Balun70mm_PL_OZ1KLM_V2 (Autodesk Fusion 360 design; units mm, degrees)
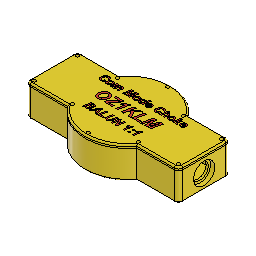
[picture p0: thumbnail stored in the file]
part number: 2026-06-13-11-17-23-040
part number: 2026-06-13-15-12-59-536
part number: 2026-06-16-10-17-01-501
part number: 2026-06-16-10-40-35-221
part number: 2026-06-16-15-31-44-028
part number: 2026-06-16-15-38-57-578
part number: 2026-06-16-16-55-37-971
part number: 2026-06-18-19-06-49-878
part number: 2026-06-18-21-17-26-018
part number: 2026-06-18-21-43-53-385
sketch "Grundtegning" plane through (0, 0, 0) normal (0, 0, 1) x axis (1, 0, 0)
  line L1 (-66.7111, -18.5) -> (-29.7111, -18.5)
  line L2 (-66.7111, 18.5) -> (-66.7111, -18.5)
  line L3 (-29.7111, 18.5) -> (-66.7111, 18.5)
  line L4 (66.7111, 18.5) -> (29.7111, 18.5)
  line L5 (66.7111, -18.5) -> (66.7111, 18.5)
  line L6 (29.7111, -18.5) -> (66.7111, -18.5)
  line L7 (-68.7111, -24.5) -> (-32.8748, -24.5)
  line L8 (-72.7111, 20.5) -> (-72.7111, -20.5)
  line L9 (-32.8748, 24.5) -> (-68.7111, 24.5)
  line L10 (68.7111, 24.5) -> (32.8748, 24.5)
  line L11 (72.7111, -20.5) -> (72.7111, 20.5)
  line L12 (32.8748, -24.5) -> (68.7111, -24.5)
  arc A1 centre (0, 0) radius 41 clockwise from (32.8748, -24.5) to (-32.8748, -24.5)
  arc A2 centre (0, 0) radius 41 clockwise from (-32.8748, 24.5) to (32.8748, 24.5)
  arc A3 centre (0, 0) radius 35 clockwise from (29.7111, -18.5) to (-29.7111, -18.5)
  arc A4 centre (0, 0) radius 35 clockwise from (-29.7111, 18.5) to (29.7111, 18.5)
  arc A5 centre (68.7111, 20.5) radius 4 clockwise from (68.7111, 24.5) to (72.7111, 20.5)
  arc A6 centre (68.7111, -20.5) radius 4 clockwise from (72.7111, -20.5) to (68.7111, -24.5)
  arc A7 centre (-68.7111, -20.5) radius 4 clockwise from (-68.7111, -24.5) to (-72.7111, -20.5)
  arc A8 centre (-68.7111, 20.5) radius 4 clockwise from (-72.7111, 20.5) to (-68.7111, 24.5)
  point P1 (0, 0)
  point P2 (0, 0)
  point P17 (72.7111, 24.5)
  point P13 (-72.7111, -24.5)
  point P14 (-72.7111, 24.5)
  point P7 (-29.7111, 18.5)
  point P8 (29.7111, 18.5)
  point P12 (-32.8748, -24.5)
  point P15 (-32.8748, 24.5)
  point P16 (32.8748, 24.5)
  coincident P1 P2
  concentric A1 A3
  horizontal L1
  vertical L2
  horizontal L3
  horizontal L4
  vertical L5
  horizontal L6
  horizontal L7
  vertical L8
  horizontal L9
  horizontal L10
  vertical L11
  horizontal L12
  concentric A3 A4
  coincident P17 L10
  coincident P17 L11
  tangent L10 A5
  tangent L11 A5
  tangent L11 A6
  tangent L12 A6
  equal A5 A6
  coincident P13 L7
  coincident P13 L8
  tangent L7 A7
  tangent L8 A7
  equal A5 A7
  coincident P14 L8
  coincident P14 L9
  tangent L8 A8
  tangent L9 A8
  equal A5 A8
  dimension "d1" diameter A3 = 70
  dimension "d2" diameter A1 = 82 (= "d1 + ( ( ( 2 + 2 + 2 ) * 2 ) * 1 mm )")
  dimension "d6" distance L1 L3 = 37 (= "( d1 / 2 ) + 2 mm")
  dimension "d10" distance L4 L6 = 37 (= "( d1 / 2 ) + 2 mm")
  dimension "d12" distance L7 L9 = 49 (= "d6 + 12 mm")
  dimension "d13" distance L2 L8 = 6
  dimension "d14" distance L5 L11 = 6 (= "d13")
  dimension "d15" distance L10 L12 = 49 (= "d12")
  dimension "d27" distance P1 L7 = 24.5 (= "d12 / 2")
  dimension "d28" distance P1 L1 = 18.5
  dimension "d29" distance P2 L6 = 18.5 (= "d10 / 2")
  dimension "d30" distance P1 L12 = 24.5 (= "d15 / 2")
  dimension "d31" distance P7 L2 = 37 (= "d6")
  dimension "d32" distance P7 P8 = 59.4222
  dimension "d33" distance P8 L5 = 37 (= "d10")
  dimension "d36" radius A2 = 41 (= "d2 / 2")
  dimension "d37" distance P12 P13 = 39.8363
  dimension "d38" distance P14 P15 = 39.8363 (= "d37")
  dimension "d39" distance P16 P17 = 39.8363 (= "d37")
  dimension "d40" radius A5 = 4
  dimension "d158" distance L8 L11 = 145.4222
sketch "SkrueHulTegning" plane through (0, 0, 0) normal (0, 0, 1) x axis (1, 0, 0)
  line L1 (69.711, 21.5) -> (-69.711, 21.5)
  line L2 (69.711, -21.5) -> (-69.711, -21.5)
  line L3 (-69.711, -21.5) -> (-69.711, 21.5)
  line L4 (69.711, -21.5) -> (69.711, 21.5)
  line L5 (69.711, 0) -> (-69.711, 0)
  line L6 (0, -38) -> (0, 38)
  circle C1 centre (0, 0) radius 38
  circle C2 centre (-68.911, 20.7) radius 1
  circle C3 centre (-68.911, -20.7) radius 1
  circle C4 centre (68.911, -20.7) radius 1
  circle C5 centre (68.911, 20.7) radius 1
  circle C6 centre (-31.3329, 21.5) radius 1
  circle C7 centre (31.3329, 21.5) radius 1
  circle C8 centre (0, 38) radius 1
  circle C9 centre (-31.3329, -21.5) radius 1
  circle C10 centre (0, -38) radius 1
  circle C11 centre (31.3329, -21.5) radius 1
  point P1 (0, 0)
  point P2 (0, 0)
  point P6 (69.711, 21.5)
  point P3 (69.711, -21.5)
  point P4 (-69.711, 21.5)
  point P5 (-69.711, -21.5)
  point P7 (-69.711, 0)
  point P8 (69.711, 0)
  point P9 (0, 38)
  point P10 (0, -38)
  point P15 (-31.3329, 21.5)
  point P16 (31.3329, 21.5)
  point P17 (0, 38)
  point P18 (-31.3329, -21.5)
  point P19 (0, -38)
  point P20 (31.3329, -21.5)
  point P11 (-68.911, 20.7)
  point P12 (-68.911, -20.7)
  point P13 (68.911, -20.7)
  point P14 (68.911, 20.7)
  coincident P1 P2
  horizontal L1
  horizontal L2
  perpendicular L2 L3
  perpendicular L2 L4
  coincident L1 P6
  coincident P3 L4
  coincident L1 P4
  coincident L2 P5
  midpoint L3 P7
  midpoint L4 P8
  coincident C1 P9
  coincident C1 P10
  perpendicular L5 L6
  coincident C1 P15
  coincident L1 P15
  coincident C1 P16
  coincident L1 P16
  coincident P9 P17
  coincident P2 L6
  coincident L2 P18
  coincident C1 P18
  coincident P10 P19
  coincident L2 P20
  coincident C1 P20
  dimension "d41" diameter C1 = 76 (= "70 mm + ( 6 mm )")
  dimension "d42" distance P2 L1 = 21.5
  dimension "d43" distance P2 L2 = 21.5
  dimension "d44" distance P2 L3 = 69.711
  dimension "d45" distance P1 L4 = 69.711
  dimension "d47" diameter C2 = 2
  dimension "d48" distance L1 P11 = 0.8 (= "d49")
  dimension "d49" distance L3 P11 = 0.8
  dimension "d50" diameter C3 = 2 (= "d47")
  dimension "d51" distance L3 P12 = 0.8 (= "d49")
  dimension "d52" distance L2 P12 = 0.8 (= "d49")
  dimension "d53" diameter C4 = 2 (= "d47")
  dimension "d54" diameter C5 = 2 (= "d47")
  dimension "d55" distance L4 P13 = 0.8 (= "d49")
  dimension "d56" distance L2 P13 = 0.8 (= "d49")
  dimension "d57" distance L4 P14 = 0.8 (= "d49")
  dimension "d58" distance L1 P14 = 0.8 (= "d49")
  dimension "d59" diameter C6 = 2 (= "d47")
  dimension "d60" diameter C7 = 2 (= "d47")
  dimension "d61" diameter C8 = 2 (= "d47")
  dimension "d62" diameter C9 = 2 (= "d47")
  dimension "d63" diameter C10 = 2 (= "d47")
  dimension "d64" diameter C11 = 2 (= "d47")
sketch "Case_Intern" plane through (0, 0, 0) normal (0, 0, 1) x axis (1, 0, 0)
  line L1 (12.6491, 3) -> (-12.6491, 3)
  line L2 (12.6491, -3) -> (-12.6491, -3)
  line L3 (9.1924, -9.1924) -> (0, 0)
  line L4 (13, 0) -> (0, 0)
  line L5 (9.1924, 9.1924) -> (0, 0)
  line L6 (-9.1924, 9.1924) -> (0, 0)
  line L7 (-9.1924, -9.1924) -> (0, 0)
  line L8 (8.3046, -10.0017) -> (-10.0017, 8.3046)
  line L9 (10.0017, -8.3046) -> (-8.3046, 10.0017)
  line L10 (8.3046, 10.0017) -> (-10.0017, -8.3046)
  line L11 (10.0017, 8.3046) -> (-8.3046, -10.0017)
  circle C1 centre (0, 0) radius 13
  circle C2 centre (0, 0) radius 15
  point P1 (0, 0)
  point P2 (0, 0)
  point P3 (0, 0)
  point P4 (-12.6491, 3)
  point P5 (12.6491, 3)
  point P6 (-12.6491, -3)
  point P7 (12.6491, -3)
  point P8 (0, 0)
  point P11 (0, 0)
  point P12 (9.1924, 9.1924)
  point P13 (0, 0)
  point P14 (-9.1924, 9.1924)
  point P15 (-9.1924, -9.1924)
  point P16 (-10.0017, 8.3046)
  point P17 (8.3046, -10.0017)
  point P18 (-8.3046, 10.0017)
  point P19 (10.0017, -8.3046)
  point P20 (-10.0017, -8.3046)
  point P21 (8.3046, 10.0017)
  point P22 (-8.3046, -10.0017)
  point P23 (10.0017, 8.3046)
  coincident P1 P2
  coincident P1 P3
  coincident C1 P4
  coincident C1 P5
  horizontal L1
  coincident C1 P6
  coincident C1 P7
  parallel L1 L2
  horizontal L4
  coincident P3 P8
  coincident P1 P11
  coincident C1 P12
  perpendicular L3 L5
  coincident P2 P13
  coincident C1 P14
  perpendicular L5 L6
  coincident C1 P15
  perpendicular L6 L7
  coincident C1 P16
  coincident C1 P17
  coincident C1 P18
  coincident C1 P19
  parallel L8 L9
  coincident C1 P20
  coincident C1 P21
  perpendicular L9 L10
  coincident C1 P22
  coincident C1 P23
  perpendicular L9 L11
  parallel L3 L8
  dimension "d159" diameter C1 = 26
  dimension "d160" diameter C2 = 30
  dimension "d161" distance L1 L2 = 6
  dimension "d162" distance P2 L2 = 3
  dimension "d163" angle L3 L4 = 45
  dimension "d164" distance L6 L8 = 1.2
  dimension "d165" distance L6 L9 = 1.2
  dimension "d166" distance L5 L10 = 1.2
  dimension "d167" distance L5 L11 = 1.2
sketch "Case_Intern_2" plane through (0, 0, 0) normal (0, 0, 1) x axis (1, 0, 0)
  line L1 (12.6491, 3) -> (-12.6491, 3)
  line L2 (12.6491, -3) -> (-12.6491, -3)
  line L3 (13, 0) -> (0, 0)
  line L4 (-4.6971, 3) -> (-10.0017, 8.3046)
  line L5 (-1.3029, 3) -> (-8.3046, 10.0017)
  line L6 (10.0017, -8.3046) -> (4.6971, -3)
  line L7 (8.3046, -10.0017) -> (1.3029, -3)
  line L8 (10.0017, 8.3046) -> (4.6971, 3)
  line L9 (8.3046, 10.0017) -> (1.3029, 3)
  line L10 (-4.6971, -3) -> (-10.0017, -8.3046)
  line L11 (-1.3029, -3) -> (-8.3046, -10.0017)
  circle C1 centre (0, 0) radius 13
  circle C2 centre (0, 0) radius 15
  point P6 (0, 0)
  point P9 (0, 0)
  point P2 (0, 0)
  point P8 (-12.6491, 3)
  point P5 (12.6491, 3)
  point P3 (-12.6491, -3)
  point P7 (12.6491, -3)
  point P10 (0, 0)
  point P4 (-10.0017, 8.3046)
  point P14 (8.3046, -10.0017)
  point P17 (-8.3046, 10.0017)
  point P18 (10.0017, -8.3046)
  point P15 (-10.0017, -8.3046)
  point P16 (8.3046, 10.0017)
  point P12 (-8.3046, -10.0017)
  point P13 (10.0017, 8.3046)
  point P1 (0, 0)
  point P19 (-4.6971, 3)
  point P20 (-1.3029, 3)
  point P21 (4.6971, -3)
  point P22 (1.3029, -3)
  point P23 (4.6971, 3)
  point P24 (1.3029, 3)
  point P25 (-4.6971, -3)
  point P26 (-1.3029, -3)
  coincident P6 P9
  coincident P2 P9
  coincident P8 C1
  coincident P5 C1
  horizontal L1
  coincident P3 C1
  coincident P7 C1
  parallel L1 L2
  horizontal L3
  coincident P2 P10
  coincident P4 C1
  coincident P14 C1
  coincident P17 C1
  coincident P18 C1
  parallel L4 L5
  coincident P15 C1
  coincident P16 C1
  coincident P12 C1
  coincident P13 C1
  coincident P1 P6
  coincident L1 P19
  coincident L1 P20
  coincident L2 P21
  coincident L2 P22
  coincident L1 P23
  coincident L1 P24
  coincident L2 P25
  coincident L2 P26
  dimension "d222" diameter C1 = 26
  dimension "d223" diameter C2 = 30
  dimension "d224" distance L1 L2 = 6
  dimension "d225" distance P6 L2 = 3
  dimension "d231" distance L8 L9 = 2.4
  dimension "d232" distance L6 L7 = 2.4
  dimension "d233" distance L10 L11 = 2.4
  dimension "d234" distance L4 L5 = 2.4
  dimension "d235" distance P1 L7 = 1.2
  dimension "d236" angle L3 L6 = 45
  dimension "d237" angle L7 L11 = 90
  dimension "d238" distance P1 L11 = 1.2
  dimension "d239" angle L3 L8 = 45
  dimension "d240" angle L5 L9 = 90
  dimension "d241" distance P1 L5 = 1.2
  dimension "d242" distance P1 L9 = 1.2
sketch "TopTegning" plane through (0, 0, 0) normal (0, 0, 1) x axis (1, 0, 0)
  line L1 (72.6153, 0) -> (-72.6153, 0)
  line L2 (0, -41.1317) -> (0, 40.7932)
  line L3 (-68.911, -39.9689) -> (-68.911, 40.0995)
  line L4 (68.911, -40.6095) -> (68.911, 39.886)
  line L5 (31.3329, 21.5) -> (-31.3329, 21.5)
  line L6 (31.3329, -21.5) -> (-31.3329, -21.5)
  line L7 (71.9932, 20.7) -> (-72.6153, 20.7)
  line L8 (72.2067, -20.7) -> (-72.557, -20.7)
  line L9 (66.7111, 16) -> (66.7111, 18.5)
  line L10 (-66.7111, 18.5) -> (-66.7111, 16)
  line L11 (66.7111, -16) -> (66.7111, -18.5)
  line L12 (-66.7111, -18.5) -> (-66.7111, -16)
  line L13 (31.1288, -16) -> (66.7111, -16)
  line L14 (-66.7111, -16) -> (-31.1288, -16)
  line L15 (-29.7111, -18.5) -> (-66.7111, -18.5)
  line L16 (66.7111, -18.5) -> (29.7111, -18.5)
  line L17 (31.1288, 16) -> (66.7111, 16)
  line L18 (-66.7111, 16) -> (-31.1288, 16)
  line L19 (-29.7111, 18.5) -> (-66.7111, 18.5)
  line L20 (66.7111, 18.5) -> (29.7111, 18.5)
  circle C1 centre (0, 0) radius 38
  circle C2 centre (-68.911, 20.7) radius 1.55
  circle C3 centre (-31.3329, 21.5) radius 1.55
  circle C4 centre (0, 38) radius 1.55
  circle C5 centre (31.3329, 21.5) radius 1.55
  circle C6 centre (68.911, 20.7) radius 1.55
  circle C7 centre (68.911, -20.7) radius 1.55
  circle C8 centre (31.3329, -21.5) radius 1.55
  circle C9 centre (0, -38) radius 1.55
  circle C10 centre (-31.3329, -21.5) radius 1.55
  circle C11 centre (-68.911, -20.7) radius 1.55
  circle C12 centre (0, 0) radius 35
  arc A1 centre (0, 0) radius 35 clockwise from (-29.7111, -18.5) to (-31.1288, -16)
  arc A2 centre (0, 0) radius 35 clockwise from (-31.1288, 16) to (-29.7111, 18.5)
  arc A3 centre (0, 0) radius 35 clockwise from (31.1288, -16) to (29.7111, -18.5)
  arc A4 centre (0, 0) radius 35 clockwise from (29.7111, 18.5) to (31.1288, 16)
  point P4 (0, 0)
  point P7 (0, 0)
  point P12 (-31.3329, 21.5)
  point P13 (31.3329, 21.5)
  point P14 (-31.3329, -21.5)
  point P15 (31.3329, -21.5)
  point P20 (-68.911, 20.7)
  point P21 (-31.3329, 21.5)
  point P22 (0, 38)
  point P23 (31.3329, 21.5)
  point P24 (68.911, 20.7)
  point P25 (68.911, -20.7)
  point P26 (31.3329, -21.5)
  point P27 (0, -38)
  point P28 (-31.3329, -21.5)
  point P29 (-68.911, -20.7)
  point P1 (0, 0)
  point P38 (0, 0)
  point P43 (-31.1288, -16)
  point P44 (31.1288, -16)
  point P45 (-31.1288, 16)
  point P46 (31.1288, 16)
  point P30 (-66.7111, 18.5)
  point P33 (-66.7111, 16)
  point P34 (-66.7111, -18.5)
  point P37 (-66.7111, -16)
  point P39 (29.7111, 18.5)
  point P40 (29.7111, -18.5)
  point P41 (-29.7111, 18.5)
  point P42 (-29.7111, -18.5)
  horizontal L1
  coincident L1 P4
  vertical L2
  coincident P4 L2
  coincident P4 P7
  vertical L3
  vertical L4
  coincident C1 P12
  coincident C1 P13
  perpendicular L3 L5
  coincident C1 P14
  coincident C1 P15
  perpendicular L2 L6
  perpendicular L4 L7
  perpendicular L4 L8
  coincident L7 P20
  coincident L3 P20
  coincident P12 P21
  coincident L2 P22
  coincident C1 P22
  coincident P13 P23
  coincident L7 P24
  coincident L4 P24
  coincident L8 P25
  coincident L4 P25
  coincident P15 P26
  coincident C1 P27
  coincident L2 P27
  coincident P14 P28
  coincident L3 P29
  coincident L8 P29
  horizontal L19
  vertical L9
  horizontal L17
  vertical L10
  horizontal L15
  vertical L11
  horizontal L13
  vertical L12
  coincident P1 P38
  coincident C12 P43
  collinear L13 L14
  coincident C12 P44
  collinear L15 L16
  coincident C12 P45
  collinear L17 L18
  coincident C12 P46
  collinear L19 L20
  concentric C1 A1
  concentric A1 A2
  concentric A3 A4
  dimension "d97" diameter C1 = 76
  dimension "d98" distance P7 L3 = 68.911
  dimension "d99" distance P7 L4 = 68.911
  dimension "d100" distance P7 L5 = 21.5
  dimension "d101" distance P7 L6 = 21.5
  dimension "d102" distance P7 L7 = 20.7
  dimension "d103" distance P7 L8 = 20.7
  dimension "d104" diameter C2 = 3.1
  dimension "d105" diameter C3 = 3.1
  dimension "d106" diameter C4 = 3.1
  dimension "d107" diameter C5 = 3.1
  dimension "d108" diameter C6 = 3.1
  dimension "d109" diameter C7 = 3.1
  dimension "d110" diameter C8 = 3.1
  dimension "d111" diameter C9 = 3.1
  dimension "d112" diameter C10 = 3.1
  dimension "d113" diameter C11 = 3.1
  dimension "d114" distance P30 P33 = 2.5
  dimension "d115" distance P34 P37 = 2.5
  dimension "d116" diameter C12 = 70
  dimension "d117" distance P4 L17 = 16
  dimension "d118" distance P4 L13 = 16
  dimension "d119" distance L9 P39 = 37
  dimension "d120" distance L11 P40 = 37
  dimension "d121" distance L10 P41 = 37
  dimension "d122" distance L12 P42 = 37
  dimension "d123" diameter A1 = 70
extrude "Extrude1" new body sketch "Grundtegning" profile of A4 L1 L2 L3 L4 L5 L6 along normal blind 3 bodies "Ext_BAL_Case_Bot"
extrude "Extrude2" add sketch "Grundtegning" profile of A4 A2 L1 L2 L3 L4 L5 L6 L7 L8 L9 L10 L11 L12 A5 A6 A7 A8 along normal blind 27
fillet "Fillet1" radius 1.5
extrude "Extrude3" sketch "SkrueHulTegning" profile of C2 C3 C4 C5 C6 C7 C8 C9 C10 C11 blind -24
sketch "PL_Ind" plane through (-72.7111, 0, 0) normal (-1, 0, 0) x axis (0, -1, 0)
  line L1 (20.5, 27) -> (20.5, 1.5)
  line L2 (-20.5, 27) -> (20.5, 27)
  line L3 (-20.5, 1.5) -> (-20.5, 27)
  line L4 (-5.6, 8.4277) -> (-5.6, 19.5723)
  line L5 (0, 27) -> (0, 0)
  line L6 (20.5, 1.5) -> (-20.5, 1.5)
  circle C1 centre (0, 14) radius 7.9
  circle C2 centre (0, 14) radius 10.1
  point P8 (-5.6, 19.5723)
  point P9 (-5.6, 8.4277)
  point P1 (0, 0)
  point P10 (0, 0)
  point P11 (0, 27)
  point P6 (0, 14)
  point P7 (0, 14)
  concentric C1 C2
  coincident C1 P8
  coincident C1 P9
  vertical L4
  coincident P1 P10
  midpoint L2 P11
  coincident P6 L5
  dimension "d76" diameter C1 = 15.8
  dimension "d77" diameter C2 = 20.2
  dimension "d78" distance P6 L4 = 5.6
  dimension "d79" distance P1 P7 = 14
extrude "Extrude5" cut sketch "PL_Ind" profile of C1 L4 against normal blind 6
extrude "Extrude4" cut sketch "PL_Ind" profile of C1 C2 against normal blind 4
sketch "PL_Ud" plane through (72.7111, 0, 0) normal (1, 0, 0) x axis (0, 1, 0)
  line L1 (20.5, 27) -> (20.5, 1.5)
  line L2 (-20.5, 27) -> (20.5, 27)
  line L3 (-20.5, 1.5) -> (-20.5, 27)
  line L4 (0, 27) -> (0, 0)
  line L5 (-5.6, 8.4277) -> (-5.6, 19.5723)
  line L6 (20.5, 1.5) -> (-20.5, 1.5)
  circle C1 centre (0, 14) radius 7.9
  circle C2 centre (0, 14) radius 10.1
  point P1 (0, 0)
  point P6 (0, 0)
  point P7 (0, 27)
  point P8 (0, 14)
  point P10 (-5.6, 19.5723)
  point P11 (-5.6, 8.4277)
  point P9 (0, 14)
  coincident P1 P6
  perpendicular L2 L4
  midpoint L2 P7
  coincident L4 P8
  concentric C1 C2
  coincident C1 P10
  coincident C1 P11
  vertical L5
  dimension "d89" diameter C1 = 15.8
  dimension "d90" diameter C2 = 20.2
  dimension "d91" distance P9 L5 = 5.6
  dimension "d92" distance P1 P9 = 14
extrude "Extrude6" cut sketch "PL_Ud" profile of C1 L5 against normal blind 6
extrude "Extrude7" cut sketch "PL_Ud" profile of C1 C2 against normal blind 4
extrude "Extrude8" add sketch "Case_Intern" profile of C1 C2 blind 2 from offset 3
extrude "Extrude10" cut sketch "Case_Intern" profile of C1 L1 L2 L3 L5 L6 L7 L8 L9 L10 L11 blind -1 from offset 3
chamfer "Chamfer1" distance 1.6
extrude "Extrude1" new body sketch "Grundtegning" profile of A4 A2 L1 L2 L3 L4 L5 L6 L7 L8 L9 L10 L11 L12 A5 A6 A7 A8 blind 3 from offset 27
extrude "Extrude2" sketch "TopTegning" profile of C2 C3 C4 C5 C6 C7 C8 C9 C10 C11 blind -3
extrude "Extrude3" sketch "TopTegning" profile of L20 L9 L18 L10 L16 L11 L14 L12 A4 blind -2.5
fillet "Fillet1" radius 1.5
extrude "Extrude6" cut sketch "Case_Intern_2" profile of C1 L7 L10 L11 L1 L2 L6 blind 1 from offset 27
extrude "Extrude5" add sketch "Case_Intern" profile of C1 C2 blind -2 from offset 27
chamfer "Chamfer1" distance 1.6
sketch "TopTekst" plane through (0, 0, 30) normal (0, 0, 1) x axis (-1, 0, 0)
  line L1 (68.7111, -23) -> (32.1131, -23)
  line L2 (71.2111, 20.5) -> (71.2111, -20.5)
  line L3 (32.1131, 23) -> (68.7111, 23)
  line L4 (-68.7111, 23) -> (-32.1131, 23)
  line L5 (-71.2111, -20.5) -> (-71.2111, 20.5)
  line L6 (-32.1131, -23) -> (-68.7111, -23)
  curve K1
  curve K2
  curve K3
  curve K4
  curve K5
  curve K6
  curve K7
  curve K8
  curve K9
  curve K10
  curve K11
  curve K12
  arc A1 centre (0, 0) radius 39.5 clockwise from (32.1131, -23) to (0.3981, -39.498)
  arc A2 centre (68.7111, -20.5) radius 2.5 clockwise from (71.2111, -20.5) to (68.7111, -23)
  arc A3 centre (68.7111, 20.5) radius 2.5 clockwise from (68.7111, 23) to (71.2111, 20.5)
  arc A4 centre (0, 0) radius 39.5 clockwise from (0.3981, 39.498) to (32.1131, 23)
  arc A5 centre (0, 38) radius 1.55 clockwise from (0.3981, 39.498) to (-0.3981, 39.498)
  arc A6 centre (0, 0) radius 39.5 clockwise from (-32.1131, 23) to (-0.3981, 39.498)
  arc A7 centre (-68.7111, 20.5) radius 2.5 clockwise from (-71.2111, 20.5) to (-68.7111, 23)
  arc A8 centre (-68.7111, -20.5) radius 2.5 clockwise from (-68.7111, -23) to (-71.2111, -20.5)
  arc A9 centre (0, 0) radius 39.5 clockwise from (-0.3981, -39.498) to (-32.1131, -23)
  arc A10 centre (0, -38) radius 1.55 clockwise from (-0.3981, -39.498) to (0.3981, -39.498)
  circle C1 centre (-31.3329, -21.5) radius 1.55
  circle C2 centre (68.911, -20.7) radius 1.55
  circle C3 centre (-68.911, -20.7) radius 1.55
  circle C4 centre (31.3329, 21.5) radius 1.55
  circle C5 centre (-31.3329, 21.5) radius 1.55
  circle C6 centre (31.3329, -21.5) radius 1.55
  circle C7 centre (-68.911, 20.7) radius 1.55
  circle C8 centre (68.911, 20.7) radius 1.55
  dimension "d266" Text1-Height = 7
  dimension "d265" Text2-Height = 10
  dimension "d541" OZ1KLM = "'OZ1KLM'"
  dimension "d267" Text3-Height = 7
emboss "Emboss1" sketch "TopTekst" Depth -1 Horizontal Distance 0 Vertical Distance 0 Rotation Angle 0
emboss "Emboss2" sketch "TopTekst" Depth -1 Horizontal Distance 0 Vertical Distance 0 Rotation Angle 0
emboss "Emboss3" sketch "TopTekst" Depth -1 Horizontal Distance 0 Vertical Distance 0 Rotation Angle 0
place_component sketch "TopTekst"
extrude "Extrude1" sketch "TopTekst" blind 1 from offset -1
fillet "Fillet2" radius 0.8
extrude "Extrude1" new body sketch "Case_Intern" profile of C1 L1 L2 L3 L5 L6 L7 L8 L9 L10 L11 blind 13 from offset 2
extrude "Extrude2" sketch "Case_Intern" profile of C1 L1 L2 L3 L6 L8 L9 blind 2
extrude "Extrude3" sketch "Case_Intern" profile of C1 L1 L2 L5 L7 L10 L11 blind -2
extrude "Extrude4" sketch "Case_Intern" profile of C1 L1 L2 L3 L5 L6 L7 L8 L9 L10 L11 blind -10
fillet "Fillet1" radius 0.6
fillet "Fillet2" radius 1
extrude "Extrude1" new body sketch "Case_Intern" profile of C1 L1 L2 L3 L5 L6 L7 L8 L9 L10 L11 blind -13 from offset 28
extrude "Extrude2" sketch "Case_Intern" profile of C1 L1 L2 L5 L7 L10 L11 blind -2
extrude "Extrude3" sketch "Case_Intern" profile of C1 L1 L2 L3 L6 L8 L9 blind 2
extrude "Extrude4" sketch "Case_Intern" profile of C1 L1 L2 L3 L5 L6 L7 L8 L9 L10 L11 blind 10
fillet "Fillet1" radius 0.6
fillet "Fillet2" radius 1
place_component sketch "Case_Intern"
extrude "Extrude1" new body sketch "Case_Intern" profile of C1 L1 L2 L3 L5 L6 L7 L8 L9 L10 L11 blind 26 from offset 2
fillet "Fillet1" sketch "Case_Intern" radius 1
extrude "Extrude1" new body sketch "Case_Intern_2" profile of C1 L7 L10 L11 L1 L2 L6 blind 13 from offset 2
extrude "Extrude2" sketch "Case_Intern_2" profile of C1 L7 L1 L2 L6 blind 2
extrude "Extrude3" sketch "Case_Intern_2" profile of C1 L10 L11 L1 L2 blind -2
extrude "Extrude4" sketch "Case_Intern_2" profile of C1 L1 L2 blind -10
fillet "Fillet1" radius 0.8
fillet "Fillet2" radius 1
extrude "Extrude1" new body sketch "Case_Intern_2" profile of C1 L7 L10 L11 L1 L2 L6 blind -13 from offset 28
extrude "Extrude2" sketch "Case_Intern_2" profile of C1 L10 L11 L1 L2 blind -2
extrude "Extrude3" sketch "Case_Intern_2" profile of C1 L7 L1 L2 L6 blind 2
extrude "Extrude4" sketch "Case_Intern_2" profile of C1 L1 L2 blind 10
fillet "Fillet1" radius 0.8
fillet "Fillet2" radius 1
place_component sketch "Case_Intern_2"
extrude "Extrude1" new body sketch "Case_Intern_2" profile of C1 L7 L10 L11 L1 L2 L6 blind 26 from offset 2
fillet "Fillet1" sketch "Case_Intern_2" radius 1
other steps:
create_component "CreateComponent1"
create_component "CreateComponent2"
create_component "CreateComponent1" sketch "TopTekst"
create_component "CreateComponent3"
create_component "CreateComponent4"
create_component "CreateComponent5" sketch "Case_Intern"
create_component "CreateComponent6"
create_component "CreateComponent7"
create_component "CreateComponent8" sketch "Case_Intern_2"
named bodies: "Ext_BAL_Case_Bot"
